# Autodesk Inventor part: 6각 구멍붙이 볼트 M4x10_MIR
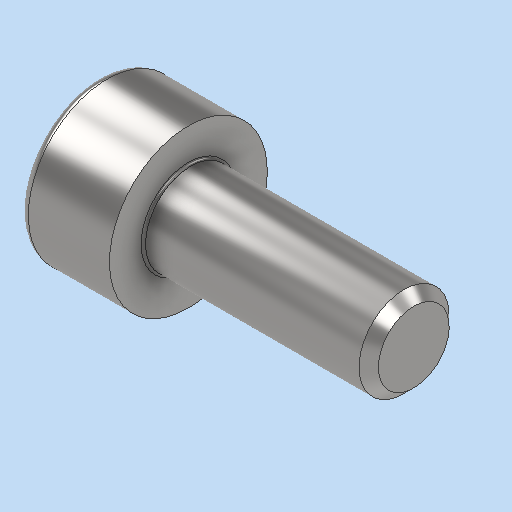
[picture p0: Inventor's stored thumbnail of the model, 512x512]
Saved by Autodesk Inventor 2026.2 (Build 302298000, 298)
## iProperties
Created: 2026-01
Part Number: 6각 구멍붙이 볼트 M4x10_MIR
Material: 강철, 연강
Description: 6각머리 태핑 나사
Document SubType Name: Modeling
Designer: PC2-07
Density: 7.85 g/cm^3
Appearance: 기본값
Author: jhkim
Sending System: Autodesk Inventor 2026
Preprocessor: ST-DEVELOPER v20.1
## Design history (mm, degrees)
derived "6각 구멍붙이 볼트 M4x10.ipt"
feature "솔리드1::6각 구멍붙이 볼트 M4x10.ipt" dims "d0" = 10
tag "피쳐 태그1"
node "솔리드1"
